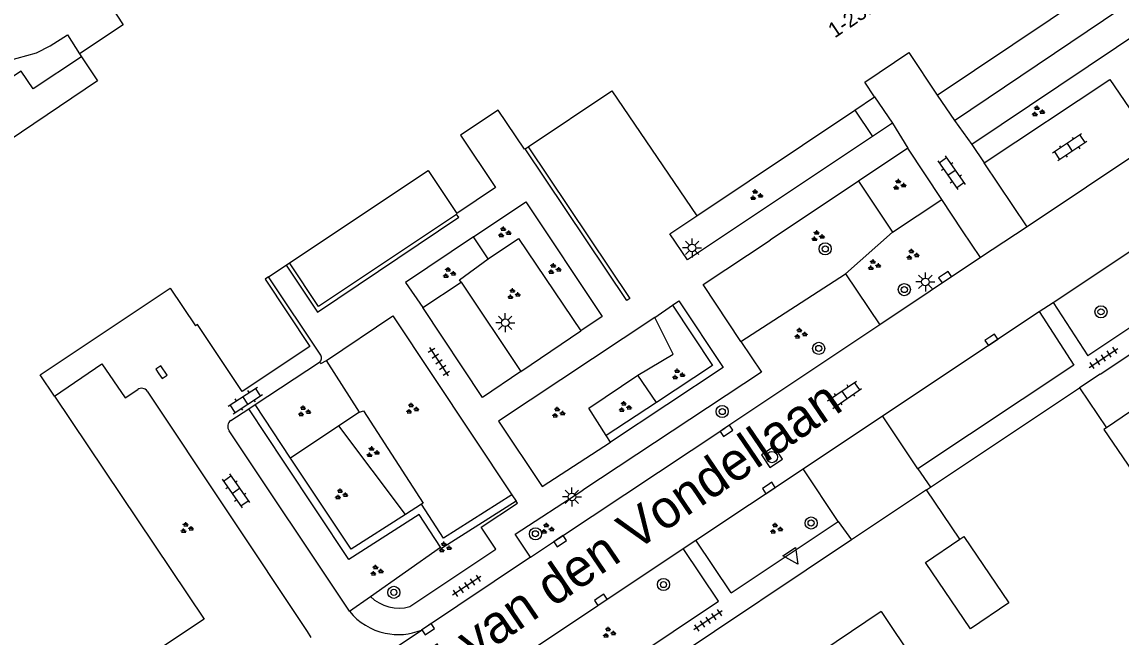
# Model space of a CAD drawing. Extents: x 137999 to 141000, y 397500 to 400501.
# Drawn here: x 138113.6 to 138186, y 399592.6 to 399633.1 of the extents above; entities that cross this region are included whole.
import ezdxf

# ---------------------------------------------------------------- set-up
doc = ezdxf.new("R2010")
doc.units = 0
for name, color, linetype in [('gg-afsc-muur', 7, 'Continuous'), ('gg-anno-huisnummerreeks BGT', 7, 'Continuous'), ('gg-anno-openbare ruimte label', 7, 'Continuous'), ('gg-bbg-bijgebouw', 7, 'Continuous'), ('gg-bbg-gedigitaliseerde bebouwing', 7, 'Continuous'), ('gg-bbg-gedigitaliseerde bijgebouw', 7, 'Continuous'), ('gg-bbg-hoofdgebouw', 7, 'Continuous'), ('gg-knt-verharding', 7, 'Continuous'), ('gg-knt-verharding nz', 7, 'Continuous'), ('gt-grn-groengrens', 7, 'Continuous'), ('gt-grn-weggrens', 7, 'Continuous'), ('gt-symb-boom', 7, 'Continuous'), ('gt-symb-groenvak', 7, 'Continuous'), ('gt-symb-klinker verharding', 7, 'Continuous'), ('gt-symb-kolk', 7, 'Continuous'), ('gt-symb-lichtmast', 7, 'Continuous'), ('gt-symb-rioolschacht', 7, 'Continuous'), ('gt-symb-tegel verharding', 7, 'Continuous'), ('gt-symb-waterafsluiter', 7, 'Continuous')]:
    doc.layers.add(name, color=color, linetype=linetype)

# ---------------------------------------------------------------- blocks, each defined once
blk = doc.blocks.new('gt0-BOOM')
at = {"layer": 'gt-symb-boom'}
for radius in [0.4, 0.2]:
    blk.add_circle((0, 0), radius, dxfattribs=at)
blk = doc.blocks.new('gt0-TEG1')
at = {"layer": 'gt-symb-tegel verharding'}
for p, q in [((-1.125, 0), (1.125, 0)), ((-0.9, -0.25), (-0.9, 0.25)), ((-0.45, -0.25), (-0.45, 0.25)), ((0, -0.25), (0, 0.25)), ((0.45, -0.25), (0.45, 0.25)), ((0.9, -0.25), (0.9, 0.25))]:
    blk.add_line(p, q, dxfattribs=at)
blk = doc.blocks.new('gt0-GRVAK')
at = {"layer": 'gt-symb-groenvak'}
for p, q in [((-0.11, 0.189), (-0.228, 0.24)), ((-0.182, 0.153), (0.088, 0.153)), ((-0.091, 0.211), (-0.156, 0.322)), ((-0.047, 0.214), (-0.047, 0.393)), ((-0.004, 0.211), (0.061, 0.322)), ((0.015, 0.189), (0.133, 0.24)), ((0.262, -0.052), (0.197, 0.059)), ((0.305, -0.049), (0.305, 0.13)), ((0.349, -0.052), (0.414, 0.059)), ((-0.245, -0.228), (-0.363, -0.177)), ((-0.318, -0.264), (-0.047, -0.264)), ((-0.226, -0.206), (-0.291, -0.095)), ((-0.183, -0.203), (-0.183, -0.024)), ((-0.139, -0.206), (-0.074, -0.095)), ((-0.12, -0.228), (-0.002, -0.177)), ((0.243, -0.074), (0.125, -0.023)), ((0.17, -0.11), (0.441, -0.11)), ((0.368, -0.074), (0.486, -0.023))]:
    blk.add_line(p, q, dxfattribs=at)
blk = doc.blocks.new('gt0-LMAST')
at = {"layer": 'gt-symb-lichtmast'}
for p, q in [((-0.182, 0.173), (-0.447, 0.438)), ((-0.005, 0.246), (-0.005, 0.621)), ((0.172, 0.173), (0.437, 0.438)), ((-0.255, -0.004), (-0.63, -0.004)), ((-0.182, -0.181), (-0.447, -0.446)), ((-0.005, -0.254), (-0.005, -0.629)), ((0.437, -0.446), (0.172, -0.181)), ((0.245, -0.004), (0.62, -0.004))]:
    blk.add_line(p, q, dxfattribs=at)
blk.add_circle((-0.005, -0.004), 0.25, dxfattribs=at)
blk = doc.blocks.new('gt0-KOLK')
at = {"layer": 'gt-symb-kolk'}
blk.add_lwpolyline([(0, 0), (0.375, 0), (0.375, 0.4), (-0.375, 0.4), (-0.375, 0), (0, 0)], dxfattribs=at)
blk = doc.blocks.new('gt0-RS')
at = {"layer": 'gt-symb-rioolschacht'}
blk.add_lwpolyline([(-0.5, -0.5), (0.5, -0.5), (0.5, 0.5), (-0.5, 0.5)], close=True, dxfattribs=at)
blk.add_circle((0, 0), 0.375, dxfattribs=at)
blk = doc.blocks.new('gt0-KL1')
at = {"layer": 'gt-symb-klinker verharding'}
for p, q in [((-1.15, 0.3), (1.15, 0.3)), ((-1, -0.3), (-1, 0.3)), ((-0.5, 0.3), (-0.5, 0.45)), ((0, -0.3), (0, 0.3)), ((0.5, 0.3), (0.5, 0.45)), ((1, -0.3), (1, 0.3)), ((-1.15, -0.3), (1.15, -0.3)), ((-0.5, -0.45), (-0.5, -0.3)), ((0.5, -0.45), (0.5, -0.3))]:
    blk.add_line(p, q, dxfattribs=at)
blk = doc.blocks.new('gt0-WAFSL')
at = {"layer": 'gt-symb-waterafsluiter'}
for p, q in [((-0.5, -0.333), (0, 0.667)), ((0, 0.667), (0.5, -0.333)), ((0.5, -0.333), (-0.5, -0.333))]:
    blk.add_line(p, q, dxfattribs=at)

msp = doc.modelspace()

# ---------------------------------------------------------------- linework, layer by layer
at = {"layer": 'gg-afsc-muur'}
for p, q in [((138173.454, 399602.44), (138183.278, 399608.983)), ((138183.278, 399608.983), (138185.055, 399606.363)), ((138173.195, 399602.268), (138173.454, 399602.44)), ((138175.396, 399599.011), (138173.195, 399602.268))]:
    msp.add_line(p, q, dxfattribs=at)
at = {"layer": 'gg-bbg-bijgebouw'}
for p, q in [((138173.14, 399597.48), (138175.396, 399599.011)), ((138175.396, 399599.011), (138175.66, 399599.19))]:
    msp.add_line(p, q, dxfattribs=at)
at = {"layer": 'gg-bbg-gedigitaliseerde bebouwing'}
msp.add_line((138170.22, 399594.26), (138175.968, 399585.659), dxfattribs=at)
at = {"layer": 'gg-bbg-gedigitaliseerde bijgebouw'}
msp.add_lwpolyline([(138175.66, 399599.19), (138178.625, 399594.821), (138176.106, 399593.112), (138173.14, 399597.48)], dxfattribs=at)
at = {"layer": 'gg-bbg-hoofdgebouw'}
for p, q in [((138117.4, 399631), (138117.534, 399630.799)), ((138168.472, 399627.284), (138169.78, 399628.16)), ((138158.06, 399620.31), (138168.472, 399627.284)), ((138146.757, 399624.731), (138146.954, 399624.864)), ((138129.853, 399616.294), (138131.009, 399617.064)), ((138131.009, 399617.064), (138131.233, 399617.213)), ((138170.22, 399594.26), (138164.484, 399590.419))]:
    msp.add_line(p, q, dxfattribs=at)
for points in [[(138173.91, 399628.27), (138186.32, 399636.61), (138185.56, 399637.74), (138205.38, 399651.07), (138204.39, 399652.52), (138205.383, 399653.194)], [(138122.006, 399635.898), (138119.44, 399634.18), (138120.281, 399632.91), (138117.4, 399631)], [(138117.534, 399630.799), (138118.59, 399629.22), (138106.86, 399621.31), (138107.25, 399620.73), (138106.308, 399620.105)], [(138169.78, 399628.16), (138169.14, 399629.12), (138172.03, 399631.07), (138173.91, 399628.27)], [(138146.954, 399624.864), (138152.47, 399628.56), (138158.06, 399620.31)], [(138146.757, 399624.731), (138146.71, 399624.7), (138144.98, 399627.28), (138142.5, 399625.64), (138144.809, 399622.185), (138142.261, 399620.473)], [(138131.233, 399617.213), (138140.374, 399623.296), (138142.261, 399620.473)], [(138129.853, 399616.294), (138129.63, 399616.146), (138132.577, 399611.717), (138128.102, 399608.746), (138125.158, 399613.17), (138125.028, 399613.084)], [(138115.744, 399608.447), (138114.81, 399609.84), (138123.37, 399615.55), (138125.028, 399613.084)], [(138197.411, 399606.207), (138193.44, 399612.06), (138185.055, 399606.363)], [(138115.744, 399608.447), (138125.6, 399593.751), (138122.728, 399591.838)], [(138185.055, 399606.363), (138184.89, 399606.251), (138187.05, 399603.07)]]:
    msp.add_lwpolyline(points, dxfattribs=at)
at = {"layer": 'gg-knt-verharding'}
for p, q in [((138175.05, 399626.6), (138212.18, 399651.63)), ((138193.522, 399636.648), (138176.18, 399625.02)), ((138169.78, 399628.16), (138170.95, 399626.43)), ((138173.91, 399628.27), (138175.05, 399626.6)), ((138168.472, 399627.284), (138169.632, 399625.551)), ((138170.95, 399626.43), (138169.632, 399625.551)), ((138170.95, 399626.43), (138171.97, 399624.77)), ((138175.05, 399626.6), (138176.18, 399625.02)), ((138171.97, 399624.77), (138168.727, 399622.608)), ((138174.207, 399621.395), (138171.97, 399624.77)), ((138176.18, 399625.02), (138177.001, 399623.803)), ((138168.727, 399622.608), (138162.888, 399618.717)), ((138181.537, 399614.615), (138192.678, 399622.029)), ((138175.57, 399619.34), (138174.207, 399621.395)), ((138156.293, 399619.126), (138158.06, 399620.31)), ((138176.751, 399617.569), (138175.57, 399619.34)), ((138179.839, 399619.598), (138176.751, 399617.569)), ((138195.03, 399618.59), (138183.82, 399611.09)), ((138176.751, 399617.569), (138170.122, 399613.144)), ((138184.64, 399609.89), (138195.88, 399617.36)), ((138133.284, 399611.139), (138129.853, 399616.294)), ((138140.016, 399614.278), (138142.537, 399615.941)), ((138142.537, 399615.941), (138146.473, 399610.067)), ((138180.614, 399614.017), (138181.537, 399614.615)), ((138181.537, 399614.615), (138183.82, 399611.09)), ((138155.288, 399613.632), (138156.465, 399614.441)), ((138180.614, 399614.017), (138182.897, 399610.492)), ((138170.122, 399613.144), (138159.914, 399606.33)), ((138146.473, 399610.067), (138150.426, 399612.738)), ((138128.959, 399607.884), (138133.216, 399610.679)), ((138182.897, 399610.492), (138172.625, 399603.662)), ((138184.64, 399609.89), (138183.278, 399608.983)), ((138127.358, 399606.833), (138128.541, 399607.61)), ((138128.541, 399607.61), (138128.959, 399607.884)), ((138155.402, 399608.02), (138152.1, 399605.841)), ((138135.19, 399594.268), (138127.251, 399606.162)), ((138148.954, 399599.056), (138159.914, 399606.33)), ((138158.006, 399598.955), (138165.077, 399603.661)), ((138167.384, 399600.196), (138165.077, 399603.661)), ((138172.625, 399603.662), (138173.454, 399602.44)), ((138145.885, 399601.949), (138146.163, 399601.533)), ((138173.195, 399602.268), (138168.26, 399598.98)), ((138160.322, 399595.484), (138167.384, 399600.196)), ((138167.384, 399600.196), (138168.26, 399598.98)), ((138147.117, 399597.827), (138148.954, 399599.056)), ((138168.26, 399598.98), (138149.074, 399586.156)), ((138157.174, 399598.401), (138158.006, 399598.955)), ((138160.322, 399595.484), (138158.006, 399598.955)), ((138145.842, 399590.86), (138157.174, 399598.401)), ((138159.49, 399594.929), (138157.174, 399598.401)), ((138147.117, 399597.827), (138139.924, 399593.036)), ((138135.19, 399594.268), (138136.56, 399595.236)), ((138148.215, 399587.406), (138159.49, 399594.929))]:
    msp.add_line(p, q, dxfattribs=at)
for points in [[(138107.287, 399627.814), (138109.79, 399629.48), (138110.73, 399629.91), (138112.64, 399630.53), (138114.57, 399631.05), (138115.46, 399631.51), (138116.6, 399632.24), (138117.4, 399631)], [(138117.534, 399630.799), (138114.35, 399628.68), (138113.55, 399629.85), (138104.031, 399623.56), (138106.308, 399620.105)], [(138177.001, 399623.803), (138185.266, 399629.309), (138187.825, 399625.557)], [(138169.632, 399625.551), (138157.44, 399617.414), (138156.293, 399619.126)], [(138146.954, 399624.864), (138153.647, 399614.879), (138153.456, 399614.737), (138146.757, 399624.731)], [(138143.346, 399618.936), (138146.794, 399621.249), (138151.838, 399613.692), (138150.426, 399612.738)], [(138131.009, 399617.064), (138133.077, 399613.972), (138142.38, 399620.224), (138142.238, 399620.412), (138133.134, 399614.355), (138131.233, 399617.213)], [(138143.346, 399618.936), (138138.875, 399615.936), (138140.016, 399614.278)], [(138160.959, 399612.04), (138158.477, 399615.791), (138162.888, 399618.717)], [(138156.465, 399614.441), (138156.877, 399614.724), (138159.795, 399610.32), (138152.368, 399605.419)], [(138146.473, 399610.067), (138143.938, 399608.348), (138140.016, 399614.278)], [(138156.465, 399614.441), (138159.102, 399610.461), (138155.402, 399608.02)], [(138133.66, 399610.797), (138138.038, 399613.73), (138145.885, 399601.949)], [(138155.288, 399613.632), (138145.005, 399606.787), (138147.886, 399602.493), (138152.368, 399605.419)], [(138160.959, 399612.04), (138162.328, 399610.012), (138150.546, 399602.244)], [(138115.744, 399608.447), (138118.87, 399610.574), (138120.394, 399608.336), (138121.227, 399608.884)], [(138133.216, 399610.679), (138133.302, 399610.583), (138133.66, 399610.797)], [(138121.859, 399608.767), (138132.403, 399592.944), (138132.632, 399592.554)], [(138147.117, 399597.827), (138146.101, 399599.359), (138150.546, 399602.244)], [(138139.16, 399594.582), (138144.82, 399598.356), (138143.855, 399599.802), (138146.26, 399601.387), (138146.163, 399601.533)]]:
    msp.add_lwpolyline(points, dxfattribs=at)
for centre, radius, start, end in [((138133.019, 399610.943), 0.33, 306.76916, 36.41301), ((138121.484, 399608.508), 0.456, 34.64181, 124.38173), ((138127.632, 399606.445), 0.475, 125.25135, 216.62804), ((138138.433, 399597.185), 2.703, 226.15092, 285.61073), ((138138.385, 399596.836), 4.099, 218.79548, 257.92388), ((138138.387, 399596.834), 4.097, 257.88586, 292.03299)]:
    msp.add_arc(centre, radius, start, end, dxfattribs=at)
at = {"layer": 'gg-knt-verharding nz'}
for p, q in [((138188.513, 399625.403), (138179.839, 399619.598)), ((138179.839, 399619.598), (138177.001, 399623.803)), ((138170.304, 399607.145), (138180.614, 399614.017)), ((138165.077, 399603.661), (138170.304, 399607.145)), ((138172.625, 399603.662), (138170.304, 399607.145))]:
    msp.add_line(p, q, dxfattribs=at)
at = {"layer": 'gt-grn-groengrens'}
for p, q in [((138168.727, 399622.608), (138170.967, 399619.247)), ((138170.967, 399619.247), (138174.207, 399621.395)), ((138144.32, 399617.485), (138143.346, 399618.936)), ((138167.869, 399616.493), (138170.967, 399619.247)), ((138160.959, 399612.04), (138167.869, 399616.493)), ((138167.869, 399616.493), (138170.122, 399613.144)), ((138135.835, 399607.378), (138133.66, 399610.797)), ((138155.402, 399608.02), (138154.184, 399609.826)), ((138130.883, 399604.089), (138128.541, 399607.61)), ((138131.299, 399604.365), (138128.959, 399607.884)), ((138135.835, 399607.378), (138134.489, 399606.486)), ((138134.489, 399606.486), (138131.299, 399604.365)), ((138138.861, 399600.652), (138134.489, 399606.486)), ((138152.368, 399605.419), (138152.1, 399605.841)), ((138145.885, 399601.949), (138141.384, 399599.098)), ((138139.921, 399601.331), (138138.861, 399600.652)), ((138141.384, 399599.098), (138139.921, 399601.331)), ((138146.163, 399601.533), (138141.236, 399598.412)), ((138141.179, 399598.499), (138139.774, 399600.643)), ((138136.56, 399595.236), (138141.179, 399598.499)), ((138141.236, 399598.412), (138141.179, 399598.499))]:
    msp.add_line(p, q, dxfattribs=at)
for points in [[(138144.32, 399617.485), (138146.314, 399618.836), (138150.426, 399612.738)], [(138142.537, 399615.941), (138142.431, 399616.105), (138144.32, 399617.485)], [(138154.184, 399609.826), (138156.514, 399611.21), (138155.288, 399613.632)], [(138152.1, 399605.841), (138150.944, 399607.66), (138154.184, 399609.826)], [(138135.835, 399607.378), (138136.1, 399607.466), (138140.031, 399601.402), (138139.921, 399601.331)], [(138139.774, 399600.643), (138135.145, 399597.678), (138130.883, 399604.089)], [(138138.861, 399600.652), (138135.289, 399598.364), (138131.299, 399604.365)]]:
    msp.add_lwpolyline(points, dxfattribs=at)
at = {"layer": 'gt-grn-weggrens'}
msp.add_line((138131.37, 399587.318), (138139.924, 399593.036), dxfattribs=at)

# ---------------------------------------------------------------- block references
at = {"layer": 'gt-symb-boom'}
for p in [(138166.523, 399618.14), (138171.736, 399615.46), (138184.692, 399613.995), (138166.096, 399611.588), (138159.737, 399607.427), (138165.595, 399600.084), (138147.43, 399599.376), (138138.103, 399595.517), (138155.87, 399596.031)]:
    msp.add_blockref('gt0-BOOM', p, dxfattribs=at)
at = {"layer": 'gt-symb-groenvak'}
for p in [(138180.525, 399627.197), (138171.388, 399622.355), (138161.96, 399621.673), (138145.365, 399619.232), (138166.01, 399618.972), (138172.255, 399617.758), (138141.722, 399616.543), (138148.661, 399616.804), (138169.719, 399617.065), (138145.972, 399615.155), (138164.882, 399612.553), (138156.815, 399609.864), (138153.308, 399607.722), (138132.18, 399607.435), (138139.293, 399607.609), (138148.921, 399607.349), (138136.69, 399604.746), (138134.609, 399601.97), (138124.439, 399599.746), (138148.2, 399599.706), (138163.273, 399599.706), (138141.446, 399598.468), (138136.951, 399596.939), (138152.266, 399592.862)]:
    msp.add_blockref('gt0-GRVAK', p, dxfattribs=at)
at = {"layer": 'gt-symb-klinker verharding'}
for p, rotation in [((138182.63, 399624.834), -146.08748741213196), ((138174.842, 399623.164), -55.181645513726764), ((138167.802, 399608.531), 34.532124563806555), ((138128.316, 399608.16), 33.2928485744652), ((138127.697, 399602.2), -55.181645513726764)]:
    msp.add_blockref('gt0-KL1', p, dxfattribs=dict(at, rotation=rotation))
at = {"layer": 'gt-symb-kolk'}
for p, rotation in [((138174.309, 399616.447), -146.34172813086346), ((138177.362, 399612.317), -146.3417281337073), ((138122.631, 399609.912), -56.2940434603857), ((138159.914, 399606.33), -146.34172813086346), ((138162.698, 399602.558), -146.34172813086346), ((138148.954, 399599.056), -146.3417281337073), ((138151.629, 399595.192), -146.34172813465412), ((138140.253, 399593.254), -146.34172813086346)]:
    msp.add_blockref('gt0-KOLK', p, dxfattribs=dict(at, rotation=rotation))
at = {"layer": 'gt-symb-lichtmast'}
for p in [(138157.759, 399618.211), (138173.126, 399615.97), (138145.45, 399613.282), (138149.84, 399601.811)]:
    msp.add_blockref('gt0-LMAST', p, dxfattribs=at)
at = {"layer": 'gt-symb-rioolschacht', "rotation": -146.3417281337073}
msp.add_blockref('gt0-RS', (138163.013, 399604.431), dxfattribs=at)
at = {"layer": 'gt-symb-tegel verharding'}
for p, rotation in [((138141.076, 399610.712), -56.8344006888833), ((138184.858, 399610.959), 33.626529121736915), ((138142.904, 399595.948), -146.500599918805), ((138158.803, 399593.677), -146.5005999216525)]:
    msp.add_blockref('gt0-TEG1', p, dxfattribs=dict(at, rotation=rotation))
at = {"layer": 'gt-symb-waterafsluiter', "rotation": -146.29404345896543}
msp.add_blockref('gt0-WAFSL', (138164.342, 399597.926), dxfattribs=at)

# ---------------------------------------------------------------- texts
at = {"layer": 'gg-anno-huisnummerreeks BGT'}
msp.add_text('1-23a', height=1, rotation=34, dxfattribs=at).set_placement((138167.147, 399631.998))
at = {"layer": 'gg-anno-openbare ruimte label'}
msp.add_text('Joost van den Vondellaan', height=2.5, rotation=34.2, dxfattribs=at).set_placement((138135.988, 399585.955))

doc.saveas('drawing.dxf')
